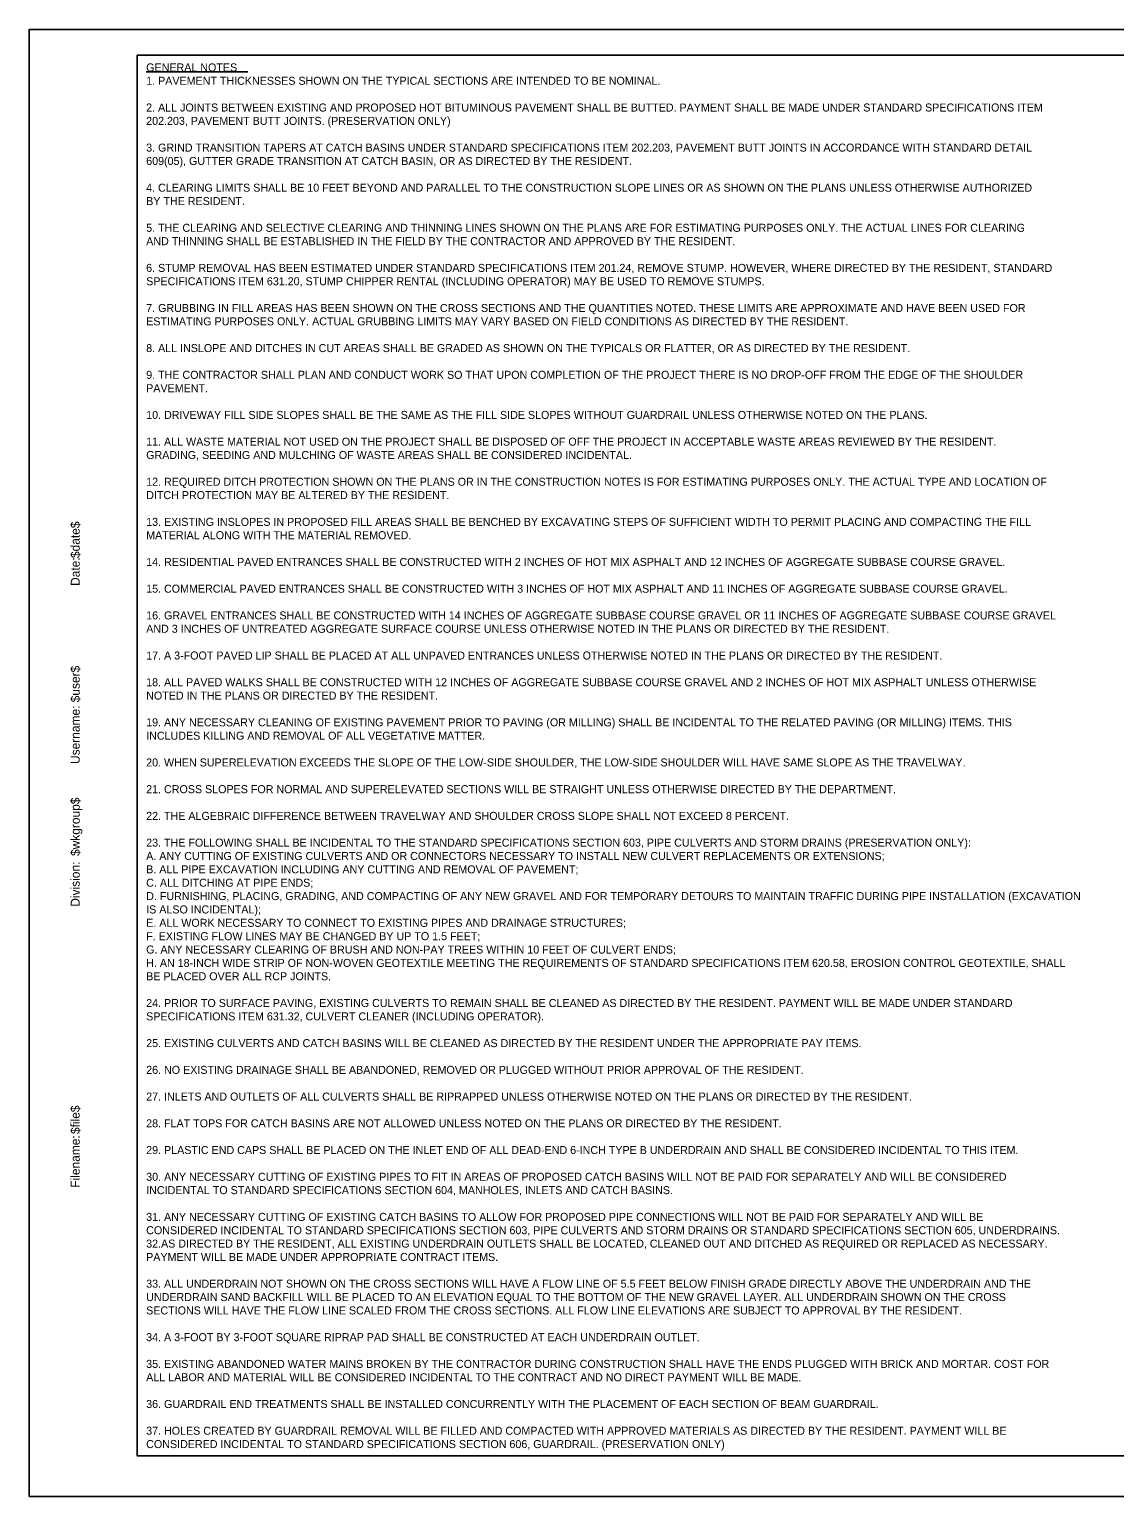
# Model space of a CAD drawing. Extents: x 850715 to 851573, y 366585 to 367135.
# Drawn here: x 850715 to 851122, y 366585 to 367135 of the extents above; entities that cross this region are included whole.
import ezdxf

# ---------------------------------------------------------------- set-up
doc = ezdxf.new("R2010")
doc.units = 0
for name, color, linetype in [('BORDER', 7, 'Continuous'), ('Default', 7, 'Continuous'), ('PLOT BOUNDARY', 7, 'Continuous')]:
    doc.layers.add(name, color=color, linetype=linetype)

msp = doc.modelspace()

# ---------------------------------------------------------------- linework, layer by layer
at = {"layer": 'BORDER'}
msp.add_lwpolyline([(850755.82, 367125.54), (851555.82, 367125.54), (851555.82, 366600.54), (850755.82, 366600.54)], close=True, dxfattribs=at)
at = {"layer": 'Default'}
msp.add_line((850759.16, 367119.36), (850797.22, 367119.36), dxfattribs=at)
at = {"layer": 'PLOT BOUNDARY'}
msp.add_lwpolyline([(850715.35, 366585.25), (851565.35, 366585.25), (851565.35, 367135.25), (850715.35, 367135.25)], close=True, dxfattribs=at)

# ---------------------------------------------------------------- texts
at = {"layer": 'BORDER'}
for s, p in [('$date$', (850734.24, 366937.07)), ('Date:', (850734.24, 366926.63)), ('$user$', (850734.24, 366883)), ('Username:', (850734.24, 366859.88)), ('$wkgroup$', (850734.24, 366825.39)), ('Division:', (850734.24, 366806.37)), ('$file$', (850734.24, 366721.17)), ('Filename:', (850734.24, 366701.04))]:
    msp.add_text(s, height=3.348, rotation=90, dxfattribs=at).set_placement(p)
at = {"layer": 'Default'}
for s, height, p in [('GENERAL NOTES', 3, (850759.16, 367119.48)), ('1. PAVEMENT THICKNESSES SHOWN ON THE TYPICAL SECTIONS ARE INTENDED TO BE NOMINAL.', 3, (850759.16, 367114.47)), ('2. ALL JOINTS BETWEEN EXISTING AND PROPOSED HOT BITUMINOUS PAVEMENT SHALL BE BUTTED. PAYMENT SHALL BE MADE UNDER STANDARD SPECIFICATIONS ITEM ', 2.99999, (850759.16, 367104.45)), ('202.203, PAVEMENT BUTT JOINTS. (PRESERVATION ONLY)', 3, (850759.16, 367099.44)), ('3. GRIND TRANSITION TAPERS AT CATCH BASINS UNDER STANDARD SPECIFICATIONS ITEM 202.203, PAVEMENT BUTT JOINTS IN ACCORDANCE WITH STANDARD DETAIL ', 2.99999, (850759.16, 367089.42)), ('609(05), GUTTER GRADE TRANSITION AT CATCH BASIN, OR AS DIRECTED BY THE RESIDENT.', 3, (850759.16, 367084.41)), ('4. CLEARING LIMITS SHALL BE 10 FEET BEYOND AND PARALLEL TO THE CONSTRUCTION SLOPE LINES OR AS SHOWN ON THE PLANS UNLESS OTHERWISE AUTHORIZED ', 2.99999, (850759.16, 367074.39)), ('BY THE RESIDENT.  ', 3, (850759.16, 367069.38)), ('5. THE CLEARING AND SELECTIVE CLEARING AND THINNING LINES SHOWN ON THE PLANS ARE FOR ESTIMATING PURPOSES ONLY. THE ACTUAL LINES FOR CLEARING ', 2.99999, (850759.16, 367059.36)), ('AND THINNING SHALL BE ESTABLISHED IN THE FIELD BY THE CONTRACTOR AND APPROVED BY THE RESIDENT.', 3, (850759.16, 367054.35)), ('6. STUMP REMOVAL HAS BEEN ESTIMATED UNDER STANDARD SPECIFICATIONS ITEM 201.24, REMOVE STUMP. HOWEVER, WHERE DIRECTED BY THE RESIDENT, STANDARD ', 2.99999, (850759.16, 367044.33)), ('SPECIFICATIONS ITEM 631.20, STUMP CHIPPER RENTAL (INCLUDING OPERATOR) MAY BE USED TO REMOVE STUMPS.   ', 2.99999, (850759.16, 367039.32)), ('7. GRUBBING IN FILL AREAS HAS BEEN SHOWN ON THE CROSS SECTIONS AND THE QUANTITIES NOTED. THESE LIMITS ARE APPROXIMATE AND HAVE BEEN USED FOR ', 2.99999, (850759.16, 367029.3)), ('ESTIMATING PURPOSES ONLY. ACTUAL GRUBBING LIMITS MAY VARY BASED ON FIELD CONDITIONS AS DIRECTED BY THE RESIDENT. ', 2.99999, (850759.16, 367024.29)), ('8. ALL INSLOPE AND DITCHES IN CUT AREAS SHALL BE GRADED AS SHOWN ON THE TYPICALS OR FLATTER, OR AS DIRECTED BY THE RESIDENT.', 2.99999, (850759.16, 367014.27)), ('9. THE CONTRACTOR SHALL PLAN AND CONDUCT WORK SO THAT UPON COMPLETION OF THE PROJECT THERE IS NO DROP-OFF FROM THE EDGE OF THE SHOULDER ', 2.99999, (850759.16, 367004.25)), ('PAVEMENT. ', 3, (850759.16, 366999.24)), ('10. DRIVEWAY FILL SIDE SLOPES SHALL BE THE SAME AS THE FILL SIDE SLOPES WITHOUT GUARDRAIL UNLESS OTHERWISE NOTED ON THE PLANS.', 2.99999, (850759.16, 366989.22)), ('11. ALL WASTE MATERIAL NOT USED ON THE PROJECT SHALL BE DISPOSED OF OFF THE PROJECT IN ACCEPTABLE WASTE AREAS REVIEWED BY THE RESIDENT. ', 2.99999, (850759.16, 366979.2)), ('GRADING, SEEDING AND MULCHING OF WASTE AREAS SHALL BE CONSIDERED INCIDENTAL.', 3, (850759.16, 366974.19)), ('12. REQUIRED DITCH PROTECTION SHOWN ON THE PLANS OR IN THE CONSTRUCTION NOTES IS FOR ESTIMATING PURPOSES ONLY. THE ACTUAL TYPE AND LOCATION OF ', 2.99999, (850759.16, 366964.17)), ('DITCH PROTECTION MAY BE ALTERED BY THE RESIDENT.', 3, (850759.16, 366959.16)), ('13. EXISTING INSLOPES IN PROPOSED FILL AREAS SHALL BE BENCHED BY EXCAVATING STEPS OF SUFFICIENT WIDTH TO PERMIT PLACING AND COMPACTING THE FILL ', 2.99999, (850759.16, 366949.14)), ('MATERIAL ALONG WITH THE MATERIAL REMOVED.', 3, (850759.16, 366944.13)), ('14. RESIDENTIAL PAVED ENTRANCES SHALL BE CONSTRUCTED WITH 2 INCHES OF HOT MIX ASPHALT AND 12 INCHES OF AGGREGATE SUBBASE COURSE GRAVEL.', 2.99999, (850759.16, 366934.11)), ('15. COMMERCIAL PAVED ENTRANCES SHALL BE CONSTRUCTED WITH 3 INCHES OF HOT MIX ASPHALT AND 11 INCHES OF AGGREGATE SUBBASE COURSE GRAVEL.', 2.99999, (850759.16, 366924.09)), ('16. GRAVEL ENTRANCES SHALL BE CONSTRUCTED WITH 14 INCHES OF AGGREGATE SUBBASE COURSE GRAVEL OR 11 INCHES OF AGGREGATE SUBBASE COURSE GRAVEL ', 2.99999, (850759.16, 366914.07)), ('AND 3 INCHES OF UNTREATED AGGREGATE SURFACE COURSE UNLESS OTHERWISE NOTED IN THE PLANS OR DIRECTED BY THE RESIDENT.', 2.99999, (850759.16, 366909.06)), ('17. A 3-FOOT PAVED LIP SHALL BE PLACED AT ALL UNPAVED ENTRANCES UNLESS OTHERWISE NOTED IN THE PLANS OR DIRECTED BY THE RESIDENT.', 2.99999, (850759.16, 366899.04)), ('18. ALL PAVED WALKS SHALL BE CONSTRUCTED WITH 12 INCHES OF AGGREGATE SUBBASE COURSE GRAVEL AND 2 INCHES OF HOT MIX ASPHALT UNLESS OTHERWISE ', 2.99999, (850759.16, 366889.02)), ('NOTED IN THE PLANS OR DIRECTED BY THE RESIDENT.', 3, (850759.16, 366884.01)), ('19. ANY NECESSARY CLEANING OF EXISTING PAVEMENT PRIOR TO PAVING (OR MILLING) SHALL BE INCIDENTAL TO THE RELATED PAVING (OR MILLING) ITEMS. THIS ', 2.99999, (850759.16, 366873.99)), ('INCLUDES KILLING AND REMOVAL OF ALL VEGETATIVE MATTER.', 3, (850759.16, 366868.98)), ('20. WHEN SUPERELEVATION EXCEEDS THE SLOPE OF THE LOW-SIDE SHOULDER, THE LOW-SIDE SHOULDER WILL HAVE SAME SLOPE AS THE TRAVELWAY.', 2.99999, (850759.16, 366858.96)), ('21. CROSS SLOPES FOR NORMAL AND SUPERELEVATED SECTIONS WILL BE STRAIGHT UNLESS OTHERWISE DIRECTED BY THE DEPARTMENT.', 2.99999, (850759.16, 366848.94)), ('22. THE ALGEBRAIC DIFFERENCE BETWEEN TRAVELWAY AND SHOULDER CROSS SLOPE SHALL NOT EXCEED 8 PERCENT.', 3, (850759.16, 366838.92)), ('23. THE FOLLOWING SHALL BE INCIDENTAL TO THE STANDARD SPECIFICATIONS SECTION 603, PIPE CULVERTS AND STORM DRAINS (PRESERVATION ONLY):', 2.99999, (850759.16, 366828.9)), ('A. ANY CUTTING OF EXISTING CULVERTS AND OR CONNECTORS NECESSARY TO INSTALL NEW CULVERT REPLACEMENTS OR EXTENSIONS;', 2.99999, (850759.16, 366823.89)), ('B. ALL PIPE EXCAVATION INCLUDING ANY CUTTING AND REMOVAL OF PAVEMENT;', 3, (850759.16, 366818.88)), ('C. ALL DITCHING AT PIPE ENDS;', 3, (850759.16, 366813.87)), ('D. FURNISHING, PLACING, GRADING, AND COMPACTING OF ANY NEW GRAVEL AND FOR TEMPORARY DETOURS TO MAINTAIN TRAFFIC DURING PIPE INSTALLATION (EXCAVATION ', 2.99999, (850759.16, 366808.86)), ('IS ALSO INCIDENTAL);', 3, (850759.16, 366803.85)), ('E. ALL WORK NECESSARY TO CONNECT TO EXISTING PIPES AND DRAINAGE STRUCTURES;', 3, (850759.16, 366798.84)), ('F. EXISTING FLOW LINES MAY BE CHANGED BY UP TO 1.5 FEET; ', 3, (850759.16, 366793.83)), ('G. ANY NECESSARY CLEARING OF BRUSH AND NON-PAY TREES WITHIN 10 FEET OF CULVERT ENDS;', 3, (850759.16, 366788.82)), ('H. AN 18-INCH WIDE STRIP OF NON-WOVEN GEOTEXTILE MEETING THE REQUIREMENTS OF STANDARD SPECIFICATIONS ITEM 620.58, EROSION CONTROL GEOTEXTILE, SHALL ', 2.99999, (850759.16, 366783.81)), ('BE PLACED OVER ALL RCP JOINTS.', 3, (850759.16, 366778.8)), ('24. PRIOR TO SURFACE PAVING, EXISTING CULVERTS TO REMAIN SHALL BE CLEANED AS DIRECTED BY THE RESIDENT. PAYMENT WILL BE MADE UNDER STANDARD ', 2.99999, (850759.16, 366768.78)), ('SPECIFICATIONS ITEM 631.32, CULVERT CLEANER (INCLUDING OPERATOR).', 3, (850759.16, 366763.77)), ('25. EXISTING CULVERTS AND CATCH BASINS WILL BE CLEANED AS DIRECTED BY THE RESIDENT UNDER THE APPROPRIATE PAY ITEMS.', 2.99999, (850759.16, 366753.75)), ('26. NO EXISTING DRAINAGE SHALL BE ABANDONED, REMOVED OR PLUGGED WITHOUT PRIOR APPROVAL OF THE RESIDENT.', 2.99999, (850759.16, 366743.73)), ('27. INLETS AND OUTLETS OF ALL CULVERTS SHALL BE RIPRAPPED UNLESS OTHERWISE NOTED ON THE PLANS OR DIRECTED BY THE RESIDENT.', 2.99999, (850759.16, 366733.71)), ('28. FLAT TOPS FOR CATCH BASINS ARE NOT ALLOWED UNLESS NOTED ON THE PLANS OR DIRECTED BY THE RESIDENT.', 2.99999, (850759.16, 366723.69)), ('29. PLASTIC END CAPS SHALL BE PLACED ON THE INLET END OF ALL DEAD-END 6-INCH TYPE B UNDERDRAIN AND SHALL BE CONSIDERED INCIDENTAL TO THIS ITEM.', 2.99999, (850759.16, 366713.67)), ('30. ANY NECESSARY CUTTING OF EXISTING PIPES TO FIT IN AREAS OF PROPOSED CATCH BASINS WILL NOT BE PAID FOR SEPARATELY AND WILL BE CONSIDERED ', 2.99999, (850759.16, 366703.65)), ('INCIDENTAL TO STANDARD SPECIFICATIONS SECTION 604, MANHOLES, INLETS AND CATCH BASINS.', 3, (850759.16, 366698.64)), ('31. ANY NECESSARY CUTTING OF EXISTING CATCH BASINS TO ALLOW FOR PROPOSED PIPE CONNECTIONS WILL NOT BE PAID FOR SEPARATELY AND WILL BE ', 2.99999, (850759.16, 366688.62)), ('CONSIDERED INCIDENTAL TO STANDARD SPECIFICATIONS SECTION 603, PIPE CULVERTS AND STORM DRAINS OR STANDARD SPECIFICATIONS SECTION 605, UNDERDRAINS.', 2.99999, (850759.16, 366683.61)), ('32.AS DIRECTED BY THE RESIDENT, ALL EXISTING UNDERDRAIN OUTLETS SHALL BE LOCATED, CLEANED OUT AND DITCHED AS REQUIRED OR REPLACED AS NECESSARY. ', 2.99999, (850759.16, 366678.6)), ('PAYMENT WILL BE MADE UNDER APPROPRIATE CONTRACT ITEMS.', 3, (850759.16, 366673.59)), ('33. ALL UNDERDRAIN NOT SHOWN ON THE CROSS SECTIONS WILL HAVE A FLOW LINE OF 5.5 FEET BELOW FINISH GRADE DIRECTLY ABOVE THE UNDERDRAIN AND THE ', 2.99999, (850759.16, 366663.57)), ('UNDERDRAIN SAND BACKFILL WILL BE PLACED TO AN ELEVATION EQUAL TO THE BOTTOM OF THE NEW GRAVEL LAYER. ALL UNDERDRAIN SHOWN ON THE CROSS ', 2.99999, (850759.16, 366658.56)), ('SECTIONS WILL HAVE THE FLOW LINE SCALED FROM THE CROSS SECTIONS. ALL FLOW LINE ELEVATIONS ARE SUBJECT TO APPROVAL BY THE RESIDENT.  ', 2.99999, (850759.16, 366653.55)), ('34. A 3-FOOT BY 3-FOOT SQUARE RIPRAP PAD SHALL BE CONSTRUCTED AT EACH UNDERDRAIN OUTLET.', 3, (850759.16, 366643.53)), ('35. EXISTING ABANDONED WATER MAINS BROKEN BY THE CONTRACTOR DURING CONSTRUCTION SHALL HAVE THE ENDS PLUGGED WITH BRICK AND MORTAR. COST FOR ', 2.99999, (850759.16, 366633.51)), ('ALL LABOR AND MATERIAL WILL BE CONSIDERED INCIDENTAL TO THE CONTRACT AND NO DIRECT PAYMENT WILL BE MADE.', 2.99999, (850759.16, 366628.5)), ('36. GUARDRAIL END TREATMENTS SHALL BE INSTALLED CONCURRENTLY WITH THE PLACEMENT OF EACH SECTION OF BEAM GUARDRAIL.', 2.99999, (850759.16, 366618.48)), ('37. HOLES CREATED BY GUARDRAIL REMOVAL WILL BE FILLED AND COMPACTED WITH APPROVED MATERIALS AS DIRECTED BY THE RESIDENT. PAYMENT WILL BE ', 2.99999, (850759.16, 366608.46)), ('CONSIDERED INCIDENTAL TO STANDARD SPECIFICATIONS SECTION 606, GUARDRAIL. (PRESERVATION ONLY)', 3, (850759.16, 366603.45))]:
    msp.add_text(s, height=height, dxfattribs=at).set_placement(p)

doc.saveas('drawing.dxf')
